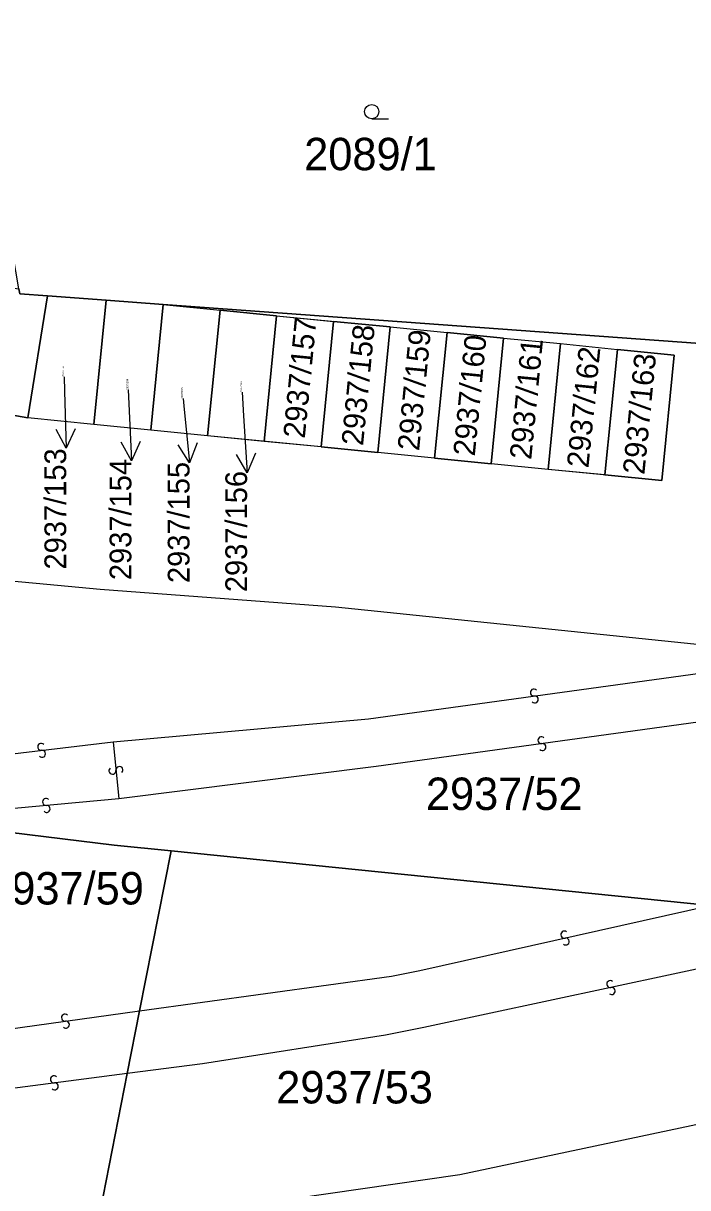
# Model space of a CAD drawing. Extents: x -596024 to -594475, y -1163820 to -1161957.
# Drawn here: x -595972.1 to -595937.3, y -1163222.9 to -1163161.8 of the extents above; entities that cross this region are included whole.
import ezdxf

# ---------------------------------------------------------------- set-up
doc = ezdxf.new("R2010")
doc.units = 0
for name, color, linetype in [('Level 1', 7, 'Continuous'), ('Level 13', 7, 'Continuous'), ('Level 3', 7, 'Continuous'), ('Level 4', 7, 'Continuous'), ('Level 5', 7, 'Continuous'), ('Level 57', 7, 'Continuous'), ('Level 60', 7, 'Continuous'), ('Vrstva 60', 7, 'Continuous')]:
    doc.layers.add(name, color=color, linetype=linetype)

msp = doc.modelspace()

# ---------------------------------------------------------------- linework, layer by layer
at = {"layer": 'Level 1'}
for points in [[(-595972.34, -1163175.74), (-595972.3, -1163176), (-595970.84, -1163176.11)], [(-595971.88, -1163182.51), (-595970.84, -1163176.11)], [(-595970.84, -1163176.11), (-595967.76, -1163176.33)], [(-595967.76, -1163176.33), (-595968.41, -1163182.85)], [(-595967.76, -1163176.33), (-595964.77, -1163176.56)], [(-595965.42, -1163183.15), (-595964.77, -1163176.56)], [(-595964.77, -1163176.56), (-595935.64, -1163178.68)], [(-595964.77, -1163176.56), (-595961.79, -1163176.85)], [(-595961.79, -1163176.85), (-595962.45, -1163183.45)], [(-595958.82, -1163177.15), (-595961.79, -1163176.85)], [(-595959.47, -1163183.74), (-595958.82, -1163177.15)], [(-595958.82, -1163177.15), (-595955.84, -1163177.44)], [(-595955.84, -1163177.44), (-595956.49, -1163184.03)], [(-595952.86, -1163177.73), (-595955.84, -1163177.44)], [(-595953.51, -1163184.33), (-595952.86, -1163177.73)], [(-595952.86, -1163177.73), (-595949.88, -1163178.03)], [(-595949.88, -1163178.03), (-595950.53, -1163184.62)], [(-595946.91, -1163178.32), (-595949.88, -1163178.03)], [(-595947.56, -1163184.91), (-595946.91, -1163178.32)], [(-595946.91, -1163178.32), (-595943.93, -1163178.61)], [(-595944.58, -1163185.21), (-595943.93, -1163178.61)], [(-595943.93, -1163178.61), (-595940.94, -1163178.92)], [(-595940.94, -1163178.92), (-595941.6, -1163185.5)], [(-595941.6, -1163185.5), (-595938.62, -1163185.79), (-595937.97, -1163179.21), (-595940.94, -1163178.92)], [(-595974.87, -1163181.97), (-595971.88, -1163182.51)], [(-595968.41, -1163182.85), (-595971.88, -1163182.51)], [(-595965.42, -1163183.15), (-595968.41, -1163182.85)], [(-595962.45, -1163183.45), (-595965.42, -1163183.15)], [(-595959.47, -1163183.74), (-595962.45, -1163183.45)], [(-595956.49, -1163184.03), (-595959.47, -1163183.74)], [(-595956.49, -1163184.03), (-595953.51, -1163184.33)], [(-595950.53, -1163184.62), (-595953.51, -1163184.33)], [(-595950.53, -1163184.62), (-595947.56, -1163184.91)], [(-595944.58, -1163185.21), (-595947.56, -1163184.91)], [(-595941.6, -1163185.5), (-595944.58, -1163185.21)], [(-595975, -1163190.85), (-595968.07, -1163191.49), (-595955.73, -1163192.42), (-595936.94, -1163194.36)], [(-595964.36, -1163205.23), (-595967.35, -1163204.93), (-595974.63, -1163204.03)], [(-595964.36, -1163205.23), (-595966.01, -1163213.62)], [(-595936.07, -1163208.09), (-595964.36, -1163205.23)], [(-595966.01, -1163213.62), (-595966.66, -1163216.91)], [(-595966.66, -1163216.91), (-595968.24, -1163224.95)]]:
    msp.add_lwpolyline(points, dxfattribs=at)
at = {"layer": 'Level 13'}
for centre, start, end in [((-595945.324, -1163196.917), 45.22605, 277.32404), ((-595945.276, -1163197.282), 225.01159, 97.60159), ((-595944.924, -1163199.418), 45.01159, 277.60159), ((-595971.17, -1163199.767), 44.21551, 276.3135), ((-595944.876, -1163199.783), 225.22605, 97.32404), ((-595971.129, -1163200.133), 224.00105, 96.59105), ((-595967.433, -1163201.018), 132.86887, 5.45887), ((-595967.066, -1163200.983), 313.08333, 185.18132), ((-595970.916, -1163202.657), 42.35271, 274.94271), ((-595970.885, -1163203.024), 222.56716, 94.66516), ((-595943.729, -1163209.62), 49.99313, 282.09112), ((-595943.651, -1163209.98), 229.77867, 102.36867), ((-595941.318, -1163212.22), 49.23509, 281.82509), ((-595941.243, -1163212.581), 229.44955, 101.54755), ((-595969.924, -1163213.977), 45.26586, 277.36386), ((-595969.876, -1163214.342), 225.05141, 97.64141), ((-595970.503, -1163217.217), 44.54159, 277.13159), ((-595970.458, -1163217.583), 224.75604, 96.85404)]:
    msp.add_arc(centre, 0.184, start, end, dxfattribs=at)
at = {"layer": 'Level 3'}
for points in [[(-595967.4, -1163199.5), (-595954, -1163198.3), (-595936.6, -1163195.9), (-595930.11, -1163194.78)], [(-595930.32, -1163197.39), (-595936.2, -1163198.4), (-595953.6, -1163200.8), (-595967.1, -1163202.5)], [(-595974.9, -1163200.4), (-595967.4, -1163199.5)], [(-595967.4, -1163199.5), (-595967.1, -1163202.5)], [(-595967.1, -1163202.5), (-595974.69, -1163203.19)], [(-595966.01, -1163213.62), (-595952.8, -1163211.8), (-595951.3, -1163211.5), (-595936.07, -1163208.09)], [(-595931.47, -1163210.3), (-595951.1, -1163214.5), (-595953.1, -1163214.9), (-595962.7, -1163216.4), (-595966.66, -1163216.91)], [(-595973.8, -1163214.7), (-595966.01, -1163213.62)], [(-595966.66, -1163216.91), (-595974.3, -1163217.9)], [(-595968.24, -1163224.95), (-595949.2, -1163222.2), (-595932.62, -1163218.69)]]:
    msp.add_lwpolyline(points, dxfattribs=at)
at = {"layer": 'Level 5'}
msp.add_line((-595953.83, -1163166.81), (-595952.955, -1163166.81), dxfattribs=at)
msp.add_circle((-595953.83, -1163166.435), 0.375, dxfattribs=at)
at = {"layer": 'Level 57'}
for p, q in [((-595969.97, -1163180.36), (-595969.948, -1163181.101)), ((-595969.948, -1163181.101), (-595969.86, -1163184.1)), ((-595966.6, -1163181.03), (-595966.569, -1163181.763)), ((-595963.73, -1163181.49), (-595963.691, -1163181.875)), ((-595960.63, -1163181.16), (-595960.554, -1163182.396)), ((-595966.569, -1163181.763), (-595966.44, -1163184.76)), ((-595963.691, -1163181.875), (-595963.39, -1163184.86)), ((-595960.554, -1163182.396), (-595960.37, -1163185.39))]:
    msp.add_line(p, q, dxfattribs=at)
for points in [[(-595969.389, -1163183.085), (-595969.86, -1163184.1), (-595970.389, -1163183.115)], [(-595965.984, -1163183.74), (-595966.44, -1163184.76), (-595966.983, -1163183.783)], [(-595962.993, -1163183.815), (-595963.39, -1163184.86), (-595963.988, -1163183.915)], [(-595959.932, -1163184.362), (-595960.37, -1163185.39), (-595960.93, -1163184.423)]]:
    msp.add_lwpolyline(points, dxfattribs=at)
at = {"layer": 'Level 60'}
for points in [[(-595934.8, -1163175.73), (-595935.01, -1163178.73), (-595935.64, -1163178.68), (-595964.77, -1163176.56), (-595967.76, -1163176.33), (-595970.84, -1163176.11), (-595972.3, -1163176), (-595972.34, -1163175.74), (-595972.5, -1163174.81), (-595975.56, -1163156.7), (-595967.15, -1163157.44), (-595937.14, -1163160.09), (-595934.14, -1163160.35), (-595934.28, -1163163.52), (-595934.41, -1163166.54), (-595934.54, -1163169.53), (-595934.67, -1163172.64)], [(-595972.34, -1163175.74), (-595972.3, -1163176), (-595970.84, -1163176.11), (-595971.88, -1163182.51), (-595974.87, -1163181.97), (-595973.93, -1163176), (-595973.85, -1163175.51)], [(-595970.84, -1163176.11), (-595967.76, -1163176.33), (-595968.41, -1163182.85), (-595971.88, -1163182.51)], [(-595967.76, -1163176.33), (-595964.77, -1163176.56), (-595965.42, -1163183.15), (-595968.41, -1163182.85)], [(-595961.79, -1163176.85), (-595962.45, -1163183.45), (-595965.42, -1163183.15), (-595964.77, -1163176.56)], [(-595958.82, -1163177.15), (-595959.47, -1163183.74), (-595962.45, -1163183.45), (-595961.79, -1163176.85)], [(-595955.84, -1163177.44), (-595956.49, -1163184.03), (-595959.47, -1163183.74), (-595958.82, -1163177.15)], [(-595952.86, -1163177.73), (-595953.51, -1163184.33), (-595956.49, -1163184.03), (-595955.84, -1163177.44)], [(-595949.88, -1163178.03), (-595950.53, -1163184.62), (-595953.51, -1163184.33), (-595952.86, -1163177.73)], [(-595946.91, -1163178.32), (-595947.56, -1163184.91), (-595950.53, -1163184.62), (-595949.88, -1163178.03)], [(-595943.93, -1163178.61), (-595944.58, -1163185.21), (-595947.56, -1163184.91), (-595946.91, -1163178.32)], [(-595940.94, -1163178.92), (-595941.6, -1163185.5), (-595944.58, -1163185.21), (-595943.93, -1163178.61)], [(-595937.97, -1163179.21), (-595938.62, -1163185.79), (-595941.6, -1163185.5), (-595940.94, -1163178.92)], [(-595975, -1163190.85), (-595968.07, -1163191.49), (-595955.73, -1163192.42), (-595936.94, -1163194.36), (-595930.11, -1163194.78), (-595930.32, -1163197.39), (-595931.1, -1163206.98), (-595931.23, -1163208.58), (-595936.07, -1163208.09), (-595964.36, -1163205.23), (-595967.35, -1163204.93), (-595974.63, -1163204.03), (-595975.47, -1163203.92), (-595977.18, -1163203.67), (-595977.14, -1163203.41), (-595976.67, -1163200.65)], [(-595967.35, -1163204.93), (-595964.36, -1163205.23), (-595966.01, -1163213.62), (-595966.66, -1163216.91), (-595968.24, -1163224.95), (-595968.72, -1163227.41), (-595969.83, -1163227.12), (-595975.07, -1163225.77), (-595976.13, -1163225.49), (-595979.21, -1163224.7), (-595978.04, -1163218.21), (-595977.47, -1163215.02), (-595975.47, -1163203.92), (-595974.63, -1163204.03)], [(-595938.74, -1163232.83), (-595947.62, -1163231.36), (-595954.46, -1163230.21), (-595961.69, -1163228.79), (-595968.72, -1163227.41), (-595968.24, -1163224.95), (-595966.66, -1163216.91), (-595966.01, -1163213.62), (-595964.36, -1163205.23), (-595936.07, -1163208.09), (-595931.23, -1163208.58), (-595931.47, -1163210.3), (-595932.62, -1163218.69), (-595934.67, -1163233.53)]]:
    msp.add_lwpolyline(points, close=True, dxfattribs=at)
at = {"layer": 'Vrstva 60'}
for points in [[(-595935.64, -1163178.68), (-595964.77, -1163176.56), (-595961.79, -1163176.85), (-595958.82, -1163177.15), (-595952.86, -1163177.73), (-595949.88, -1163178.03), (-595946.91, -1163178.32), (-595943.93, -1163178.61), (-595940.94, -1163178.92), (-595937.97, -1163179.21), (-595938.62, -1163185.79), (-595944.58, -1163185.21), (-595947.56, -1163184.91), (-595950.53, -1163184.62), (-595953.51, -1163184.33), (-595956.49, -1163184.03), (-595962.45, -1163183.45), (-595965.42, -1163183.15), (-595968.41, -1163182.85), (-595971.88, -1163182.51), (-595974.87, -1163181.97)], [(-595975, -1163190.85), (-595968.07, -1163191.49), (-595955.73, -1163192.42), (-595936.94, -1163194.36)]]:
    msp.add_lwpolyline(points, dxfattribs=at)

# ---------------------------------------------------------------- texts
at = {"layer": 'Level 4'}
for s, p in [('2089/1', (-595957.373, -1163169.51)), ('2937/52', (-595950.988, -1163203.08)), ('2937/59', (-595974.003, -1163208.04)), ('2937/53', (-595958.84, -1163218.48))]:
    msp.add_text(s, height=1.7, dxfattribs=at).set_placement(p)
for s, height, rotation, p in [('2937/157', 1.14, 84.3669, (-595957.345, -1163183.611)), ('2937/158', 1.14, 84.37536, (-595954.288, -1163183.996)), ('2937/159', 1.14, 84.3669, (-595951.347, -1163184.264)), ('2937/160', 1.14, 84.3669, (-595948.426, -1163184.543)), ('2937/161', 1.14, 84.37536, (-595945.464, -1163184.723)), ('2937/162', 1.14, 84.27213, (-595942.464, -1163185.16)), ('2937/163', 1.14, 84.35835, (-595939.53, -1163185.508)), ('2937/153', 0.1, 90, (-595969.97, -1163180.36)), ('2937/154', 0.1, 90, (-595966.6, -1163181.03)), ('2937/155', 0.1, 90, (-595963.73, -1163181.49)), ('2937/156', 0.1, 90, (-595960.63, -1163181.16))]:
    msp.add_text(s, height=height, rotation=rotation, dxfattribs=at).set_placement(p)
at = {"layer": 'Level 57'}
for s, p in [('2937/153', (-595969.86, -1163190.462)), ('2937/154', (-595966.44, -1163191.019)), ('2937/155', (-595963.39, -1163191.174)), ('2937/156', (-595960.37, -1163191.649))]:
    msp.add_text(s, height=1.14, rotation=90, dxfattribs=at).set_placement(p)

doc.saveas('drawing.dxf')
